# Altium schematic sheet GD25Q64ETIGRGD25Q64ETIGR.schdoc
size 127 x 101 mm
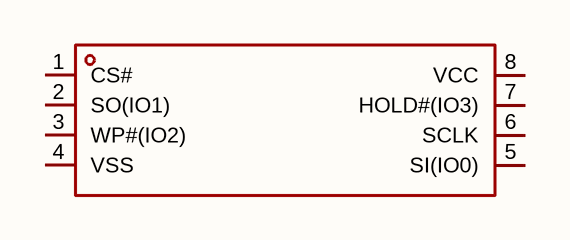
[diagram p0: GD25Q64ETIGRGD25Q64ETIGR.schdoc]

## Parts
U?  gd25q64etigr  [SOIC-8_L4.9-W3.9-P1.27-LS6.0-BL]  (value not drawn)

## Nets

Not connected (* = marked no-connect by the designer): U? 1(CS#) 2(SO(IO1)) 3(WP#(IO2)) 4(VSS) 5(SI(IO0)) 6(SCLK) 7(HOLD#(IO3)) 8(VCC)

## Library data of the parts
U? = gd25q64etigr: 接口类型:SPI;存储容量:64Mbit;时钟频率(fc):133MHz;; Manufacturer: GigaDevice(兆易创新); AddInBom: yes; ModelId: e81d2f7d937b4a6ab1dca543ff5d56a4; ModelName: SOIC-8_L4.9-W3.9-H1.7-LS6.0-P1.27; ModelTransform: 192.913,236.22,0,0,0,0,0,0,0; Interface: SPI; Memory Size: 64Mbit; Clock Frequency: 133MHz; Voltage - Supply: 2.7V~3.6V; Standby Supply Current: 12uA; Program / Erase Cycles: 100000次; Page Programming Time (Tpp): 500us; Block Erase Time(tBE): 250ms@(64KB); Data Retention - TDR (Year): 20年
